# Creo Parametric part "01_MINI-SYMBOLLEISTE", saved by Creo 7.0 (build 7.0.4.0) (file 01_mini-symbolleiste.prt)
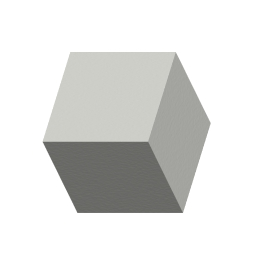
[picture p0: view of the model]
Units: millimeter Kilogram Sec (mmKs); MM, KILOGRAM, SECS
Materials in the file: S235JRG2

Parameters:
  PTC_MATERIAL_NAME = "S235JRG2"
  BENENNUNG = "Symbolleiste"
  DATUM = "XX.XX.XX"
  ERSTELLER = "ARINDA"
  TEILETYP = "Fertigungsteil"
  SELECT_EN_NAME = "S235JRG2"
  SELECT_DIN_NAME = "RSt37-2"
  SELECT_DIN_NUMBER = "1.0038"
  SELECT_ASTM_NAME = "A 283 M Grade 2"
  MATERIAL_GROUP = "ME_ST_Baustahl"
  STANDARD_EN_DELIVERYSPEC = "DIN EN 10025"
  STANDARD_DIN_DELIVERYSPEC = "DIN 17100"

Other parameters: MASSE

Created from: ARINDA-STARTTEIL.PRT

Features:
  1. coordinate system "CS0"
  2. datum plane "DTM1", "T_RECHTS_Y-Z"
  3. datum plane "DTM2", "T_OBEN_X-Z"
  4. datum plane "DTM3", "T_VORNE_X-Y"
  5. datum axis "T_X-ACHSE"
  6. datum axis "A_1"
  7. datum axis "A_2"
  8. extrusion "Profil 1"
  9. sketch "Skizze 1"
  10. feature "Profil 2"

Other named items: T_BASIC, T_Y-ACHSE, T_Z-ACHSE, DATUM_TAG_A, GP0, DRF1, VORNE, ANNOT_LAYER_STATE0001

Layers: 00_STD-ACHSEN, 00_STD-EBENEN, 00_STD-KOORDSYS, 01_KURVEN, FLAECHEN, KURVENELEMENTE, SAMMELFLÄCHEN, VOLUMENGEOMETRIE

Notes: �⫽ | 0.1Ⓜ | A

Surfaces: 12 plane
